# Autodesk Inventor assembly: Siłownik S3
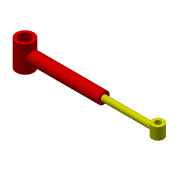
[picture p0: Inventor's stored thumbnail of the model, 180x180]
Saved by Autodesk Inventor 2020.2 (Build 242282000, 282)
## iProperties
Manager: www.cadconsulting.pl
Company: Fabian Stasiak CAD Consulting
Created: 2006-08
Part Number: Siłownik S3
Document SubType Name: Assembly
Designer: F.Stasiak
Author: F.Stasiak
Subject: Zbiór ćwiczeń. Autodesk Inventor 2020. Kurs podstawowy
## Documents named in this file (3)
- C:\2020_Kurs_podstawowy\R6 Zespoły\Lustro\Siłownik S3.iam
- C:\2020_Kurs_podstawowy\R6 Zespoły\Lustro\Cyl3.ipt
- C:\2020_Kurs_podstawowy\R6 Zespoły\Lustro\T3.ipt
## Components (2 placed, 2 different names)
1. Cyl3:1 — Zestawiający:1
2. T3:1 — Zestawiający:1
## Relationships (1: Mate 1)
- Zestawiający:1 [Mate]: Cyl3:1 ↔ T3:1
